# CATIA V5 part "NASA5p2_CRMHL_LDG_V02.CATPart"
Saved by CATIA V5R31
Part number: Part3
Bounding box of the stored display mesh (mm): x 2349.5 to 65074.801, y -0.001 to 29462.246, z 449.085 to 8715.756
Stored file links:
  C:\Users\ww962c\Desktop\CATIA Working\CRM-HL\03 HLPW5\TC3\NTF5p2_CRMHL_LDG_V02.CATPart
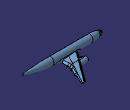
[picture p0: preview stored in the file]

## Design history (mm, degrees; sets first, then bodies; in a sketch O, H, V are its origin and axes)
Set1 "surfaces"
  DatumSurface1 "FUSE"
  DatumSurface2 "WBF"
  DatumSurface3 "NACELLE"
  DatumSurface4 "CHINE"
  DatumSurface5 "PYLON"
  DatumSurface6 "IBSLAT"
  DatumSurface7 "OBSLAT"
  DatumSurface8 "WING"
  DatumSurface9 "FLAP_COVE"
  DatumSurface10 "WING_TE"
  DatumSurface11 "SLAT_BRACKETS"
  DatumSurface12 "IBFLAP"
  DatumSurface13 "OBFLAP"
  DatumSurface14 "FTF"
Body1 (main body)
